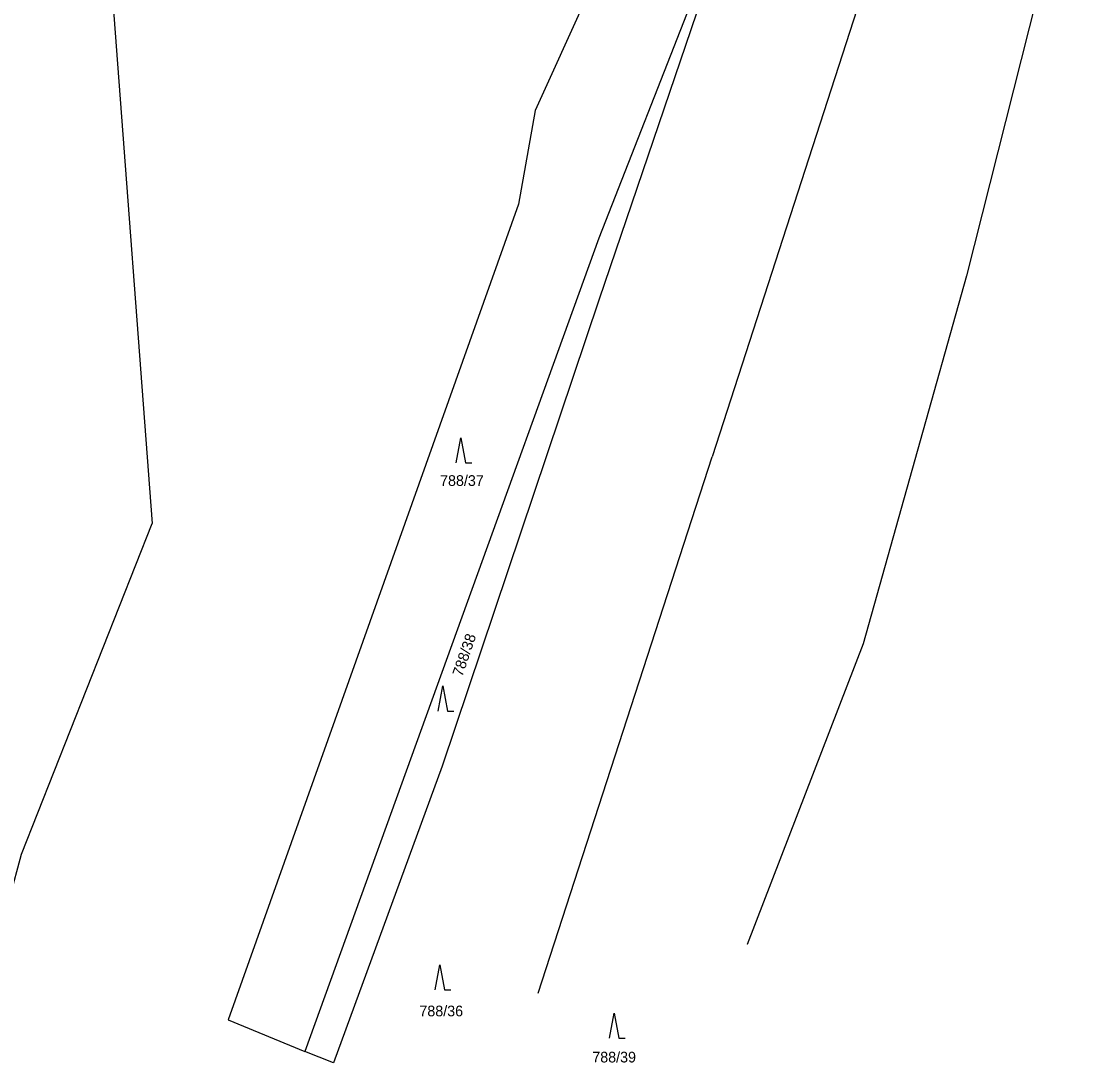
# Model space of a CAD drawing. Extents: x -759060 to -757386, y -1172273 to -1170948.
# Drawn here: x -757575.9 to -757408.6, y -1171339.8 to -1171174 of the extents above; entities that cross this region are included whole.
import ezdxf

# ---------------------------------------------------------------- set-up
doc = ezdxf.new("R2010")
doc.units = 0
for name, color, linetype in [('Vrstva 1', 7, 'Continuous'), ('Vrstva 2', 7, 'Continuous'), ('Vrstva 3', 7, 'Continuous')]:
    doc.layers.add(name, color=color, linetype=linetype)

msp = doc.modelspace()

# ---------------------------------------------------------------- linework, layer by layer
at = {"layer": 'Vrstva 1'}
for p, q in [((-757473.48, -1171142.7), (-757494.18, -1171188.26)), ((-757458.28, -1171142.75), (-757484.05, -1171208.58)), ((-757458.28, -1171142.75), (-757483.99, -1171218.27)), ((-757433.93, -1171144.15), (-757466, -1171243.38)), ((-757408.63, -1171147.49), (-757425.57, -1171214.58)), ((-757562.52, -1171155.07), (-757555.07, -1171253.96)), ((-757494.18, -1171188.26), (-757496.84, -1171203.18)), ((-757496.84, -1171203.18), (-757542.97, -1171332.91)), ((-757484.05, -1171208.58), (-757530.79, -1171337.93)), ((-757425.57, -1171214.58), (-757442, -1171273.13)), ((-757483.99, -1171218.27), (-757508.98, -1171292.57)), ((-757493.71, -1171328.66), (-757466, -1171243.38)), ((-757575.86, -1171306.56), (-757555.07, -1171253.96)), ((-757442, -1171273.13), (-757460.45, -1171320.92)), ((-757508.98, -1171292.57), (-757526.22, -1171339.78)), ((-757578.49, -1171316.23), (-757575.86, -1171306.56)), ((-757460.45, -1171320.92), (-757460.45, -1171320.92)), ((-757493.71, -1171328.66), (-757493.71, -1171328.66)), ((-757542.97, -1171332.91), (-757530.79, -1171337.93)), ((-757542.97, -1171332.91), (-757542.97, -1171332.91)), ((-757526.22, -1171339.78), (-757530.79, -1171337.93)), ((-757526.22, -1171339.78), (-757526.22, -1171339.78))]:
    msp.add_line(p, q, dxfattribs=at)
at = {"layer": 'Vrstva 3'}
for points in [[(-757506.75, -1171244.32), (-757506, -1171240.32), (-757505.25, -1171244.32), (-757504.25, -1171244.32)], [(-757509.6, -1171283.79), (-757508.85, -1171279.79), (-757508.1, -1171283.79), (-757507.1, -1171283.79)], [(-757510.07, -1171328.17), (-757509.32, -1171324.17), (-757508.57, -1171328.17), (-757507.57, -1171328.17)], [(-757482.36, -1171335.85), (-757481.61, -1171331.85), (-757480.86, -1171335.85), (-757479.86, -1171335.85)]]:
    msp.add_lwpolyline(points, dxfattribs=at)

# ---------------------------------------------------------------- texts
at = {"layer": 'Vrstva 2'}
for s, p in [('788/37', (-757509.293, -1171247.98)), ('788/36', (-757512.583, -1171332.36)), ('788/39', (-757485.083, -1171339.7))]:
    msp.add_text(s, height=1.7, dxfattribs=at).set_placement(p)
msp.add_text('788/38', height=1.7, rotation=71.21865, dxfattribs=at).set_placement((-757505.764, -1171278.425))

doc.saveas('drawing.dxf')
